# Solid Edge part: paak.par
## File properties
Author: Mac
Template: Normal.par
Last saved by: Mac
Revision: 1
Application: Solid Edge
Density: 7750,000 kg/m^3
Accuracy: 0,990
Material: Stainless steel
Face Style: Steel
Fill Style: ANSI32(Steel)
Virtual Style: Stainless steel
Coef. of Thermal Exp: 1.6e-05
Thermal Conductivity: 17.0
Specific Heat: 502.0
Modulus of Elasticity: 193053196000.0
Poission's Ratio: 0.29
Yield Stress: 310264065.0
Ultimate Stress: 641212401.0
Elongation: 0.0
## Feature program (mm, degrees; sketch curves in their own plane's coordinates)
sketch for "unnamed Protrusion 1" plane through (0, 0, 0) normal (0, 0, 1) x-axis (1, 0, 0)
  line (-20, 10) -> (0, 10)
  line (0, 10) -> (0, 0)
  line (0, 0) -> (-20, 0)
  line (-20, 0) -> (-20, 10)
extrude "unnamed Protrusion 1" add finite 10 along +normal
sketch for "ExtrudedProtrusion_2" #1 plane through (-10, 5, 10) normal (0, 0, 1) x-axis (1, 0, 0)
  circle centre (9.3079, 4.2965) radius 0.1
sketch for "ExtrudedProtrusion_2" #2 plane through (-10, 5, 10) normal (0, 0, 1) x-axis (1, 0, 0)
  circle centre (9.3079, 3.9162) radius 0.1
sketch for "ExtrudedProtrusion_2" #3 plane through (-10, 5, 10) normal (0, 0, 1) x-axis (1, 0, 0)
  circle centre (9.3079, 2.9454) radius 0.4
extrude "ExtrudedProtrusion_2" add finite 1 along +normal
sketch for "ExtrudedCutout_1" #1 plane through (-0.6921, 7.9454, 11) normal (0, 0, 1) x-axis (0, 1, 0)
  circle centre (0, 0) radius 0.38
sketch for "ExtrudedCutout_1" #2 plane through (-0.6921, 7.9454, 11) normal (0, 0, 1) x-axis (0, 1, 0)
  circle centre (0.9709, 0) radius 0.08
extrude "ExtrudedCutout_1" cut finite 10 along -normal
thinwall "Thinwall_2"  Thickness = 0.04 mm
sketch for "unnamed Cutout 1" plane through (-0.6921, 9.2965, 11) normal (0, 0, 1) x-axis (0, 1, 0)
  circle centre (0, 0) radius 0.08
extrude "unnamed Cutout 1" cut through along -normal
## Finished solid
Body 1: solid body, 25 faces, 40 edges, 16 vertices.
  Faces by surface: plane 17, cylinder 8
  Edges by curve: line 24, circle 16
Bounding box of the edges (mm): 20.000 x 10.000 x 11.000, from (-20, 0, 0) to (0, 10, 11).
Cylindrical faces by radius (mm): R0.08 x2, R0.1 x2, R0.12 x1, R0.38 x1, R0.4 x1, R0.42 x1
Planar faces by outward normal: +x 2, +y 2, +z 5, -x 2, -y 2, -z 4
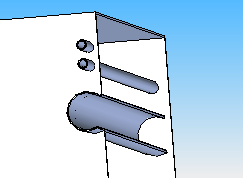
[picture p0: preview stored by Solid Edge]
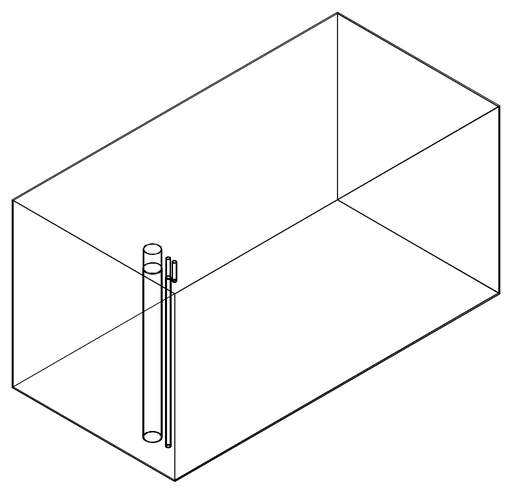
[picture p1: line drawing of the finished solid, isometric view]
